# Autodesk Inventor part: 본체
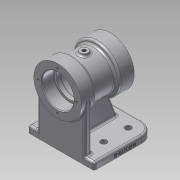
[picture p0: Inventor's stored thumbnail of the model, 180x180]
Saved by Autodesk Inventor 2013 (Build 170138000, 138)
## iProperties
Created: 2020-06
Part Number: 본체
Material: 알루미늄 6061
Document SubType Name: Modeling
Designer: a
Density: 2.71 g/cm^3
Mass: 728.075 g
Surface Area: 641.489 cm^2
Volume: 268.662 cm^3
Author: a
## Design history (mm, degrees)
sketch "스케치1"
  geometry: L1 (0, 39)-(0, -39); L2 (0, 39)-(35, 39); L3 (35, 39)-(35, 17); L4 (35, 17)-(29, 17); L5 (29, 17)-(29, -17); L6 (29, -17)-(35, -17); L7 (35, -17)-(35, -39); L8 (35, -39)-(0, -39); 2 further points
  constraints: 16 end point, 4 parallel, 2 perpendicular, 1 coincident, 1 collinear, 1 midpoint, 1 vertical
  dimensions: "d0" = 78 distance of L1.start L1.end; "d2" = 70 diameter of L3 L1; "d3" = 70 diameter of L7 L1; "d4" = 58 diameter of L5 L1; "d5" = 22 distance of L2.end L3.end; "d6" = 22 distance of L6.end L7.end
revolve "회전1" sketch "스케치1" stored, may be unused: angle "d7" = 90 deg
sketch "스케치2"
  geometry: L1 (-35, 39)-(35, 39) reference; L2 (35, 39)-(35, 17) reference; L3 (35, 17)-(29, 17) reference; L4 (29, 17)-(29, -17) reference; L5 (29, -17)-(35, -17) reference; L6 (35, -17)-(35, -39) reference; L7 (35, -39)-(-35, -39) reference; L8 (-35, -39)-(-35, -17) reference; L9 (-35, -17)-(-29, -17) reference; L10 (-29, -17)-(-29, 17) reference; L11 (-29, 17)-(-35, 17) reference; L12 (-35, 17)-(-35, 39) reference; L13 (0, 39)-(0, -39); L14 (0, 39)-(23.5, 39); L15 (23.5, 39)-(23.5, 21); L16 (23.5, 21)-(20, 21); L17 (20, 21)-(20, 15); L18 (20, 15)-(23, 15); L19 (23, 15)-(23, -15); L20 (23, -15)-(20, -15); L21 (20, -15)-(20, -21); L22 (20, -21)-(23.5, -21); L23 (23.5, -21)-(23.5, -39); L24 (0, -39)-(23.5, -39); 1 further point
  constraints: 24 end point, 6 parallel, 4 perpendicular, 2 midpoint, 2 point on line
  dimensions: "d8" = 47 diameter of L15 L13; "d10" = 47 diameter of L23 L13; "d11" = 46 diameter of L19 L13; "d12" = 40 diameter of L17 L13; "d13" = 40 diameter of L21 L13; "d14" = 18 distance of L14.end L15.end; "d15" = 6 distance of L16.end L17.end; "d16" = 30 distance of L18.end L19.end; "d17" = 18 distance of L22.end L23.end
revolve "회전2" sketch "스케치2" stored, may be unused: angle "d18" = 90 deg
node "작업 평면2"
sketch "스케치4"
  geometry: C1 r 6 at (0, 0); 1 further point
  constraints: 1 centre point, 1 coincident
  dimensions: "d22" = 12 diameter of C1
extrude "돌출1" join sketch "스케치4" stored distance "d23" = 10; taper "d24" = 0 deg
sketch "스케치5"
  geometry: C1 r 6 at (0, 0) reference; 1 further point
  constraints: 1 coincident
hole "구멍1" sketch "스케치5" at (0, 0) diameter "d25" = 5.188; stored, may be unused: countersink angle "d29" = 90 deg, drill point angle "d31" = 118 deg; dims "d26" = 30, "d27" = 4, "d28" = 2, "d30" = 30
sketch "스케치6" dims "d32" = 57
  geometry: C1 r 23.5 at (0, 0) reference; C2 r 35 at (0, 0) reference; 2 further points
  constraints: 2 vertical alignment, 1 coincident, 2 other
hole "구멍2" sketch "스케치6" at (0, 28.5) diameter "d33" = 3.242; stored, may be unused: countersink angle "d37" = 90 deg, drill point angle "d39" = 118 deg; dims "d34" = 10, "d35" = 4, "d36" = 2, "d38" = 12
node "작업 평면3"
sketch "스케치7"
  geometry: L1 (-35, 39)-(35, 39) reference; L2 (-49, 34)-(49, 34); L3 (49, 34)-(49, -56); L4 (49, -56)-(-49, -56); L5 (-49, -56)-(-49, 34); 2 further points
  constraints: 8 end point, 2 parallel, 1 horizontal, 1 midpoint, 1 perpendicular, 1 vertical alignment
  dimensions: "d44" = 98 distance of L3.end L4.end; "d45" = 90 distance of L2.end L3.end; "d46" = 5 distance between parallel lines of L1 L2
extrude "돌출2" join sketch "스케치7" distance "d47" = 10; taper "d48" = 0 deg
fillet "모깎기1" dims "d49" = 20
sketch "스케치8"
  geometry: C1 r 4.5 at (-29, 36); C2 r 4.5 at (29, 36); C3 r 4.5 at (-29, 0); C4 r 4.5 at (29, 0); A1 r 20 centre (-29, 36) between (-29, 56) and (-49, 36) reference; A2 r 20 centre (29, 36) between (49, 36) and (29, 56) reference; 1 further point
  constraints: 4 centre point, 2 coincident, 2 vertical alignment
  dimensions: "d53" = 9 diameter of C1; "d54" = 9 diameter of C2; "d55" = 9 diameter of C3; "d56" = 9 diameter of C4; "d57" = 36 distance of C3.centre A1.centre; "d58" = 36 distance of C4.centre A2.centre
extrude "돌출3" cut sketch "스케치8" distance "d59" = 10; taper "d60" = 0 deg
sketch "스케치9"
  geometry: L1 (-49, -34)-(49, -34) reference; L2 (-35, -34)-(35, -34); L3 (35, -34)-(35, -24); L4 (35, -24)-(-35, -24); L5 (-35, -24)-(-35, -34); 2 further points
  constraints: 8 end point, 2 parallel, 1 horizontal, 1 midpoint, 1 perpendicular, 1 point on line, 1 vertical alignment
  dimensions: "d61" = 70 distance of L3.end L4.end; "d63" = 10 distance of L4.end L2.start
extrude "돌출4" join sketch "스케치9" stored distance "d64" = 10; taper "d65" = 0 deg
sketch "스케치10"
  geometry: L1 (29, 6)-(32, 6) reference; L2 (32, 6)-(32, 2.594) reference; L3 (32, 2.594)-(23, 2.594) reference; L4 (23, 2.594)-(23, 15) reference; L5 (23, 15)-(20, 15) reference; L6 (20, 15)-(20, 21) reference; L7 (20, 21)-(23.5, 21) reference; L8 (23.5, 21)-(23.5, 39) reference; L9 (23.5, 39)-(26.879, 39) reference; L10 (26.879, 39)-(26.879, 27) reference; L11 (26.879, 27)-(28.5, 26.026) reference; L12 (28.5, 26.026)-(30.121, 27) reference; L13 (30.121, 27)-(30.121, 39) reference; L14 (30.121, 39)-(35, 39) reference; L15 (35, 39)-(35, 17) reference; L16 (35, 17)-(29, 17) reference; L17 (29, 17)-(29, 6) reference; L18 (23.5, -39)-(23.5, -21) reference; L19 (23.5, -21)-(20, -21) reference; L20 (20, -21)-(20, -15) reference; L21 (20, -15)-(23, -15) reference; L22 (23, -15)-(23, -2.594) reference; L23 (23, -2.594)-(32, -2.594) reference; L24 (32, -2.594)-(32, -6) reference; L25 (32, -6)-(29, -6) reference; L26 (29, -6)-(29, -17) reference; L27 (29, -17)-(35, -17) reference; L28 (35, -17)-(35, -39) reference; L29 (35, -39)-(30.121, -39) reference; L30 (30.121, -39)-(30.121, -27) reference; L31 (30.121, -27)-(28.5, -26.026) reference; L32 (28.5, -26.026)-(26.879, -27) reference; L33 (26.879, -27)-(26.879, -39) reference; L34 (26.879, -39)-(23.5, -39) reference; L35 (-80, -56)-(-80, 34) reference; L36 (-80, 34)-(-35, 34) reference; L37 (-35, 34)-(-35, 39) reference; L38 (-35, 39)-(-30.121, 39) reference; L39 (-30.121, 39)-(-30.121, 27) reference; L40 (-30.121, 27)-(-28.5, 26.026) reference; L41 (-28.5, 26.026)-(-26.879, 27) reference; L42 (-26.879, 27)-(-26.879, 39) reference; L43 (-26.879, 39)-(-23.5, 39) reference; L44 (-23.5, 39)-(-23.5, 21) reference; L45 (-23.5, 21)-(-20, 21) reference; L46 (-20, 21)-(-20, 15) reference; L47 (-20, 15)-(-23, 15) reference; L48 (-23, 15)-(-23, -15) reference; L49 (-23, -15)-(-20, -15) reference; L50 (-20, -15)-(-20, -21) reference; L51 (-20, -21)-(-23.5, -21) reference; L52 (-23.5, -21)-(-23.5, -39) reference; L53 (-23.5, -39)-(-26.879, -39) reference; L54 (-26.879, -39)-(-26.879, -27) reference; L55 (-26.879, -27)-(-28.5, -26.026) reference; L56 (-28.5, -26.026)-(-30.121, -27) reference; L57 (-30.121, -27)-(-30.121, -39) reference; L58 (-30.121, -39)-(-35, -39) reference; L59 (-35, -39)-(-35, -17) reference; L60 (-35, -17)-(-29, -17) reference; L61 (-29, -17)-(-29, 17) reference; L62 (-29, 17)-(-35, 17) reference; L63 (-35, 17)-(-35, 24) reference; L64 (-35, 24)-(-70, 24) reference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; 1 further point
  constraints: 2 end point, 2 point on line
  dimensions: "d66" = 12 distance of L65.end L67.start; "d67" = 70 deg angle of L67 L65
feature "리브1" sketch "스케치10" dims "d68" = 1, "d69" = 10, "d70" = 0, "d71" = 0, "d72" = 1, "d73" = 1
sketch "스케치11"
  geometry: 3 further points
  constraints: 1 other
  dimensions: "d74" = 45 horizontal distance of point (0, 0) point (45, 4); "d75" = 4 vertical distance of point (0, 0) point (45, 4)
feature "엠보싱1" sketch "스케치11" dims "d76" = 0.5, "d77" = 0
fillet "모깎기2" dims "d78" = 3
fillet "모깎기3" dims "d79" = 0.3
chamfer "모따기1" distance "d80" = 1; stored, may be unused: second distance "d81" = 2, angle "d82" = 45 deg
fillet "모깎기4" dims "d83" = 3
fillet "모깎기5" dims "d84" = 3
fillet "모깎기6" dims "d85" = 3
fillet "모깎기7" dims "d86" = 3
fillet "모깎기8" dims "d87" = 3
fillet "모깎기9" dims "d88" = 3
fillet "모깎기10" dims "d89" = 3
fillet "모깎기11" dims "d90" = 3
fillet "모깎기12" dims "d91" = 3
fillet "모깎기13" dims "d92" = 3
node "솔리드1"
pattern_circular "원형 패턴1" dims angle "d41" = 360 deg
mirror "대칭1"
node "절단 모서리 투영1"
node "절단 모서리 투영2"
other parameters: "d21" = 32
